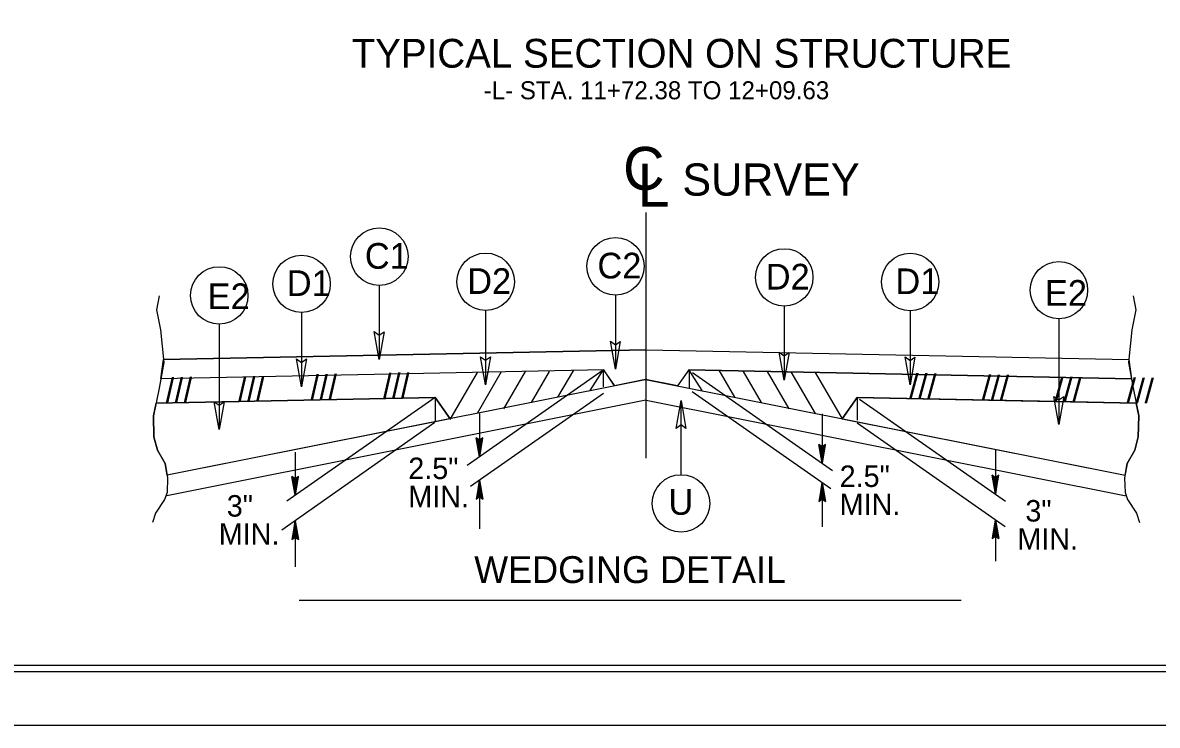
# Model space of a CAD drawing. Extents: x 575722 to 576066, y -53107 to -52774.
# Drawn here: x 575878.83 to 575926.06, y -52908.76 to -52879.49 of the extents above; entities that cross this region are included whole.
import ezdxf

# ---------------------------------------------------------------- set-up
doc = ezdxf.new("R2010")
doc.units = 0
for name, color, linetype in [('Prop Dimension Text', 7, 'Continuous'), ('Prop DSN Text', 7, 'Continuous'), ('Sheet Cutting Line CELL', 7, 'Continuous'), ('Sheet Plot Border Inside CELL', 7, 'Continuous'), ('Sheet Plot Border Outside CELL', 7, 'Continuous'), ('Sheet Typical CELL', 7, 'Continuous'), ('Typical Text Label CELL', 7, 'Continuous')]:
    doc.layers.add(name, color=color, linetype=linetype)

msp = doc.modelspace()

# ---------------------------------------------------------------- linework, layer by layer
at = {"layer": 'Prop DSN Text'}
for p, q in [((575904.783, -52897.636), (575904.783, -52887.4)), ((575893.675, -52890.431), (575893.675, -52893.523)), ((575903.509, -52890.835), (575903.509, -52893.927)), ((575904.783, -52897.636), (575904.783, -52890.645)), ((575910.532, -52891.296), (575910.532, -52894.388)), ((575890.439, -52891.566), (575890.439, -52894.658)), ((575898.101, -52891.479), (575898.101, -52894.571)), ((575915.776, -52891.487), (575915.776, -52894.579)), ((575921.968, -52891.827), (575921.968, -52896.224)), ((575887.012, -52892.048), (575887.012, -52896.444)), ((575904.783, -52893.114), (575884.694, -52893.515)), ((575884.694, -52893.515), (575904.783, -52893.114)), ((575904.783, -52893.114), (575924.873, -52893.515)), ((575904.785, -52893.114), (575924.873, -52893.515)), ((575884.58, -52894.322), (575884.694, -52893.515)), ((575924.873, -52893.515), (575924.988, -52894.322)), ((575903.021, -52893.954), (575884.58, -52894.322)), ((575903.021, -52893.954), (575884.58, -52894.322)), ((575897.752, -52894.06), (575896.61, -52896.016)), ((575902.998, -52893.969), (575897.338, -52897.933)), ((575898.754, -52894.039), (575897.744, -52895.774)), ((575899.747, -52894.02), (575898.84, -52895.574)), ((575900.747, -52894.022), (575899.995, -52895.309)), ((575901.755, -52893.97), (575901.1, -52895.093)), ((575902.45, -52894.813), (575902.995, -52893.961)), ((575902.995, -52893.961), (575902.995, -52894.661)), ((575903.472, -52894.616), (575903.021, -52893.954)), ((575903.021, -52893.975), (575903.472, -52894.616)), ((575906.56, -52893.954), (575906.094, -52894.616)), ((575906.56, -52893.954), (575906.094, -52894.616)), ((575906.531, -52893.969), (575906.56, -52893.97)), ((575906.56, -52893.954), (575924.988, -52894.322)), ((575924.988, -52894.322), (575906.56, -52893.954)), ((575907.117, -52894.813), (575906.572, -52893.961)), ((575906.572, -52893.961), (575906.572, -52894.732)), ((575906.714, -52894.061), (575912.545, -52898.145)), ((575907.811, -52893.97), (575908.467, -52895.093)), ((575908.819, -52894.022), (575909.571, -52895.309)), ((575909.819, -52894.02), (575910.727, -52895.574)), ((575910.812, -52894.039), (575911.823, -52895.774)), ((575911.816, -52894.06), (575912.94, -52895.987)), ((575904.813, -52894.349), (575884.845, -52898.344)), ((575904.753, -52894.349), (575903.472, -52894.616)), ((575904.753, -52894.349), (575924.722, -52898.344)), ((575906.094, -52894.616), (575904.753, -52894.349)), ((575895.995, -52895.102), (575884.384, -52895.334)), ((575884.384, -52895.334), (575895.995, -52895.102)), ((575895.995, -52895.102), (575889.83, -52899.419)), ((575896.627, -52895.989), (575895.995, -52895.102)), ((575895.995, -52895.102), (575895.995, -52896.115)), ((575895.995, -52895.102), (575896.625, -52895.987)), ((575903.011, -52894.938), (575897.472, -52898.816)), ((575906.706, -52894.855), (575912.48, -52898.898)), ((575913.571, -52895.102), (575912.94, -52895.987)), ((575912.941, -52895.987), (575913.571, -52895.102)), ((575913.571, -52895.102), (575925.183, -52895.334)), ((575913.571, -52895.102), (575913.571, -52896.043)), ((575921.852, -52895.268), (575913.571, -52895.102)), ((575913.665, -52895.167), (575919.746, -52899.426)), ((575904.775, -52895.209), (575884.838, -52899.197)), ((575904.791, -52895.209), (575924.774, -52899.206)), ((575906.237, -52898.321), (575906.237, -52895.229)), ((575925.183, -52895.334), (575921.852, -52895.268)), ((575895.995, -52896.113), (575893.973, -52896.518)), ((575896.625, -52895.987), (575895.995, -52896.113)), ((575897.853, -52895.776), (575897.853, -52897.571)), ((575912.119, -52895.788), (575912.119, -52897.846)), ((575912.94, -52895.987), (575915.594, -52896.518)), ((575893.973, -52896.518), (575884.845, -52898.344)), ((575895.99, -52896.147), (575889.617, -52900.632)), ((575913.571, -52896.166), (575919.735, -52900.484)), ((575915.594, -52896.518), (575924.722, -52898.344)), ((575897.853, -52897.571), (575897.714, -52896.784)), ((575897.853, -52896.887), (575897.714, -52896.784)), ((575897.853, -52897.571), (575897.734, -52896.799)), ((575897.754, -52896.814), (575897.853, -52897.571)), ((575897.853, -52897.571), (575897.773, -52896.828)), ((575897.794, -52896.843), (575897.853, -52897.571)), ((575897.853, -52897.571), (575897.814, -52896.857)), ((575897.834, -52896.872), (575897.853, -52897.571)), ((575897.853, -52897.571), (575897.993, -52896.784)), ((575897.993, -52896.784), (575897.853, -52896.887)), ((575897.973, -52896.799), (575897.853, -52897.571)), ((575897.853, -52897.571), (575897.952, -52896.814)), ((575897.932, -52896.828), (575897.853, -52897.571)), ((575897.853, -52897.571), (575897.912, -52896.843)), ((575897.893, -52896.857), (575897.853, -52897.571)), ((575897.853, -52897.571), (575897.873, -52896.872)), ((575897.853, -52896.887), (575897.853, -52897.571)), ((575912.119, -52897.846), (575911.98, -52897.058)), ((575912.119, -52897.161), (575911.98, -52897.058)), ((575912.119, -52897.846), (575912.258, -52897.058)), ((575912.258, -52897.058), (575912.119, -52897.161)), ((575890.177, -52897.387), (575890.177, -52899.177)), ((575912.119, -52897.846), (575912, -52897.073)), ((575912.02, -52897.088), (575912.119, -52897.846)), ((575912.119, -52897.846), (575912.039, -52897.102)), ((575912.059, -52897.117), (575912.119, -52897.846)), ((575912.119, -52897.846), (575912.079, -52897.131)), ((575912.098, -52897.146), (575912.119, -52897.846)), ((575912.237, -52897.073), (575912.119, -52897.846)), ((575912.119, -52897.846), (575912.218, -52897.088)), ((575912.198, -52897.102), (575912.119, -52897.846)), ((575912.119, -52897.846), (575912.178, -52897.117)), ((575912.159, -52897.131), (575912.119, -52897.846)), ((575912.119, -52897.846), (575912.139, -52897.146)), ((575912.119, -52897.161), (575912.119, -52897.846)), ((575919.328, -52897.271), (575919.328, -52899.132)), ((575890.177, -52899.177), (575890.037, -52898.389)), ((575890.177, -52898.49), (575890.037, -52898.389)), ((575890.177, -52899.177), (575890.057, -52898.403)), ((575890.079, -52898.418), (575890.177, -52899.177)), ((575890.177, -52899.177), (575890.098, -52898.432)), ((575890.118, -52898.446), (575890.177, -52899.177)), ((575890.177, -52899.177), (575890.138, -52898.461)), ((575890.157, -52898.476), (575890.177, -52899.177)), ((575890.177, -52899.177), (575890.316, -52898.389)), ((575890.316, -52898.389), (575890.177, -52898.49)), ((575890.296, -52898.403), (575890.177, -52899.177)), ((575890.177, -52899.177), (575890.277, -52898.418)), ((575890.257, -52898.432), (575890.177, -52899.177)), ((575890.177, -52899.177), (575890.236, -52898.446)), ((575890.217, -52898.461), (575890.177, -52899.177)), ((575890.177, -52899.177), (575890.197, -52898.476)), ((575919.328, -52899.132), (575919.189, -52898.346)), ((575919.328, -52898.447), (575919.189, -52898.346)), ((575919.328, -52899.132), (575919.209, -52898.36)), ((575919.228, -52898.374), (575919.328, -52899.132)), ((575919.328, -52899.132), (575919.248, -52898.388)), ((575919.268, -52898.404), (575919.328, -52899.132)), ((575919.328, -52899.132), (575919.287, -52898.418)), ((575919.307, -52898.433), (575919.328, -52899.132)), ((575919.328, -52899.132), (575919.467, -52898.346)), ((575919.467, -52898.346), (575919.328, -52898.447)), ((575919.446, -52898.36), (575919.328, -52899.132)), ((575919.328, -52899.132), (575919.426, -52898.374)), ((575919.407, -52898.388), (575919.328, -52899.132)), ((575919.328, -52899.132), (575919.387, -52898.404)), ((575919.367, -52898.418), (575919.328, -52899.132)), ((575919.328, -52899.132), (575919.347, -52898.433)), ((575919.328, -52898.447), (575919.328, -52899.132)), ((575890.177, -52898.49), (575890.177, -52899.177)), ((575897.853, -52898.549), (575897.714, -52899.337)), ((575897.734, -52899.321), (575897.853, -52898.549)), ((575897.853, -52898.549), (575897.754, -52899.307)), ((575897.773, -52899.291), (575897.853, -52898.549)), ((575897.853, -52898.549), (575897.794, -52899.278)), ((575897.814, -52899.264), (575897.853, -52898.549)), ((575897.853, -52898.549), (575897.834, -52899.249)), ((575897.853, -52898.549), (575897.853, -52900.571)), ((575897.853, -52898.549), (575897.993, -52899.337)), ((575897.853, -52899.234), (575897.853, -52898.549)), ((575897.873, -52899.249), (575897.853, -52898.549)), ((575897.853, -52898.549), (575897.893, -52899.264)), ((575897.912, -52899.278), (575897.853, -52898.549)), ((575897.853, -52898.549), (575897.932, -52899.291)), ((575897.952, -52899.307), (575897.853, -52898.549)), ((575897.853, -52898.549), (575897.973, -52899.321)), ((575912.119, -52898.645), (575911.98, -52899.433)), ((575912, -52899.417), (575912.119, -52898.645)), ((575912.119, -52898.645), (575912.02, -52899.403)), ((575912.039, -52899.387), (575912.119, -52898.645)), ((575912.119, -52898.645), (575912.059, -52899.374)), ((575912.079, -52899.36), (575912.119, -52898.645)), ((575912.119, -52898.645), (575912.098, -52899.345)), ((575912.119, -52898.645), (575912.119, -52900.486)), ((575912.119, -52898.645), (575912.258, -52899.433)), ((575912.119, -52899.33), (575912.119, -52898.645)), ((575912.139, -52899.345), (575912.119, -52898.645)), ((575912.119, -52898.645), (575912.159, -52899.36)), ((575912.178, -52899.374), (575912.119, -52898.645)), ((575912.119, -52898.645), (575912.198, -52899.387)), ((575912.218, -52899.403), (575912.119, -52898.645)), ((575912.119, -52898.645), (575912.237, -52899.417)), ((575897.714, -52899.337), (575897.853, -52899.234)), ((575897.853, -52899.234), (575897.993, -52899.337)), ((575911.98, -52899.433), (575912.119, -52899.33)), ((575912.119, -52899.33), (575912.258, -52899.433)), ((575890.177, -52900.239), (575890.037, -52901.026)), ((575890.059, -52901.012), (575890.177, -52900.239)), ((575890.177, -52900.239), (575890.079, -52900.997)), ((575890.098, -52900.982), (575890.177, -52900.239)), ((575890.177, -52900.239), (575890.118, -52900.967)), ((575890.138, -52900.954), (575890.177, -52900.239)), ((575890.177, -52900.239), (575890.157, -52900.94)), ((575890.177, -52900.239), (575890.177, -52902.153)), ((575890.177, -52900.239), (575890.316, -52901.026)), ((575890.177, -52900.924), (575890.177, -52900.239)), ((575890.197, -52900.94), (575890.177, -52900.239)), ((575890.177, -52900.239), (575890.217, -52900.954)), ((575890.237, -52900.967), (575890.177, -52900.239)), ((575890.177, -52900.239), (575890.257, -52900.982)), ((575890.277, -52900.997), (575890.177, -52900.239)), ((575890.177, -52900.239), (575890.296, -52901.012)), ((575919.328, -52900.197), (575919.189, -52900.985)), ((575919.209, -52900.97), (575919.328, -52900.197)), ((575919.328, -52900.197), (575919.228, -52900.956)), ((575919.248, -52900.941), (575919.328, -52900.197)), ((575919.328, -52900.197), (575919.268, -52900.926)), ((575919.287, -52900.911), (575919.328, -52900.197)), ((575919.328, -52900.197), (575919.307, -52900.897)), ((575919.328, -52900.197), (575919.328, -52901.926)), ((575919.328, -52900.197), (575919.467, -52900.985)), ((575919.328, -52900.882), (575919.328, -52900.197)), ((575919.347, -52900.897), (575919.328, -52900.197)), ((575919.328, -52900.197), (575919.367, -52900.911)), ((575919.387, -52900.926), (575919.328, -52900.197)), ((575919.328, -52900.197), (575919.407, -52900.941)), ((575919.426, -52900.956), (575919.328, -52900.197)), ((575919.328, -52900.197), (575919.446, -52900.97)), ((575890.037, -52901.026), (575890.177, -52900.924)), ((575890.177, -52900.924), (575890.316, -52901.026)), ((575919.189, -52900.985), (575919.328, -52900.882)), ((575919.328, -52900.882), (575919.467, -52900.985))]:
    msp.add_line(p, q, dxfattribs=at)
for points in [[(575884.508, -52890.864), (575884.4, -52891.453), (575884.561, -52892.289), (575884.703, -52893.644), (575884.508, -52894.713), (575884.276, -52895.871), (575884.294, -52896.745), (575884.437, -52897.296), (575884.758, -52897.85), (575884.864, -52898.455), (575884.847, -52899.061), (575884.739, -52899.347), (575884.366, -52899.917), (575884.241, -52900.309)], [(575925.059, -52890.864), (575925.166, -52891.453), (575925.005, -52892.289), (575924.863, -52893.644), (575925.059, -52894.713), (575925.291, -52895.871), (575925.273, -52896.745), (575925.13, -52897.296), (575924.809, -52897.85), (575924.703, -52898.455), (575924.72, -52899.061), (575924.827, -52899.347), (575925.2, -52899.917), (575925.325, -52900.309)], [(575884.844, -52898.344), (575884.758, -52897.85), (575884.437, -52897.296), (575884.294, -52896.745), (575884.276, -52895.871), (575884.383, -52895.334)], [(575924.722, -52898.344), (575924.809, -52897.85), (575925.13, -52897.296), (575925.273, -52896.745), (575925.291, -52895.871), (575925.183, -52895.334)]]:
    msp.add_lwpolyline(points, dxfattribs=at)
for points in [[(575893.875, -52892.363), (575893.675, -52893.523), (575893.469, -52892.356), (575893.675, -52892.505)], [(575893.875, -52892.363), (575893.675, -52893.523), (575893.469, -52892.356), (575893.675, -52892.505)], [(575903.709, -52892.767), (575903.509, -52893.927), (575903.303, -52892.761), (575903.509, -52892.909)], [(575903.709, -52892.767), (575903.509, -52893.927), (575903.303, -52892.761), (575903.509, -52892.909)], [(575910.732, -52893.228), (575910.532, -52894.388), (575910.326, -52893.222), (575910.532, -52893.37)], [(575910.732, -52893.228), (575910.532, -52894.388), (575910.326, -52893.222), (575910.532, -52893.37)], [(575890.639, -52893.498), (575890.439, -52894.658), (575890.233, -52893.491), (575890.439, -52893.639)], [(575890.639, -52893.498), (575890.439, -52894.658), (575890.233, -52893.491), (575890.439, -52893.639)], [(575898.301, -52893.411), (575898.101, -52894.571), (575897.895, -52893.405), (575898.101, -52893.553)], [(575898.301, -52893.411), (575898.101, -52894.571), (575897.895, -52893.405), (575898.101, -52893.553)], [(575915.976, -52893.419), (575915.776, -52894.579), (575915.57, -52893.413), (575915.776, -52893.561)], [(575915.976, -52893.419), (575915.776, -52894.579), (575915.57, -52893.413), (575915.776, -52893.561)], [(575922.167, -52895.064), (575921.968, -52896.224), (575921.761, -52895.058), (575921.968, -52895.206)], [(575887.211, -52895.285), (575887.012, -52896.444), (575886.805, -52895.278), (575887.012, -52895.426)], [(575887.211, -52895.285), (575887.012, -52896.444), (575886.805, -52895.278), (575887.012, -52895.426)], [(575906.037, -52896.389), (575906.237, -52895.229), (575906.443, -52896.395), (575906.237, -52896.247)], [(575906.037, -52896.389), (575906.237, -52895.229), (575906.443, -52896.395), (575906.237, -52896.247)]]:
    msp.add_lwpolyline(points, close=True, dxfattribs=at)
for centre in [(575893.675, -52889.235), (575903.509, -52889.639), (575910.532, -52890.1), (575890.439, -52890.37), (575898.102, -52890.283), (575915.776, -52890.291), (575921.967, -52890.631), (575887.011, -52890.852), (575906.237, -52899.517)]:
    msp.add_circle(centre, 1.196, dxfattribs=at)
at = {"layer": 'Sheet Cutting Line CELL'}
msp.add_line((575796.575, -52908.762), (575964.975, -52908.762), dxfattribs=at)
at = {"layer": 'Sheet Plot Border Inside CELL'}
msp.add_lwpolyline([(575964.525, -52801.007), (575797.875, -52801.007), (575797.875, -52906.517), (575964.525, -52906.517)], close=True, dxfattribs=at)
at = {"layer": 'Sheet Plot Border Outside CELL'}
msp.add_lwpolyline([(575964.975, -52798.762), (575796.575, -52798.762), (575796.575, -52908.762), (575964.975, -52908.762)], close=True, dxfattribs=at)
at = {"layer": 'Sheet Typical CELL'}
msp.add_lwpolyline([(575963.275, -52801.262), (575813.275, -52801.262), (575813.275, -52906.262), (575963.275, -52906.262)], close=True, dxfattribs=at)
at = {"layer": 'Typical Text Label CELL'}
msp.add_line((575890.337, -52903.542), (575917.902, -52903.542), dxfattribs=at)

# ---------------------------------------------------------------- texts
at = {"layer": 'Prop Dimension Text'}
msp.add_text('TYPICAL SECTION ON STRUCTURE', height=1.2, dxfattribs=at).set_placement((575892.525, -52881.363))
at = {"layer": 'Prop DSN Text'}
for s, height, p in [('-L- STA. 11+72.38 TO 12+09.63', 0.75, (575898.023, -52882.679)), ('C', 1.79, (575903.823, -52886.454)), ('L', 1.79, (575904.424, -52887.157)), ('SURVEY ', 1.3422, (575906.293, -52886.695)), ('C1', 1.0708, (575893.075, -52889.74)), ('C2', 1.0708, (575902.756, -52890.145)), ('D1', 1.0708, (575889.824, -52890.875)), ('D2', 1.0708, (575897.333, -52890.789)), ('D2', 1.0708, (575909.763, -52890.606)), ('D1', 1.0708, (575915.161, -52890.797)), ('E2', 1.0708, (575886.531, -52891.422)), ('E2', 1.0708, (575921.385, -52891.283)), ('2.5"', 0.8948, (575894.882, -52898.503)), ('2.5"', 0.8948, (575912.84, -52898.831)), ('MIN.', 0.8948, (575894.882, -52899.676)), ('U', 1.071, (575905.714, -52899.991)), (' 3"', 0.8948, (575886.994, -52900.066)), ('MIN.', 0.8948, (575912.84, -52900.004)), (' 3"', 0.8948, (575920.239, -52900.272)), ('MIN.', 0.8948, (575886.994, -52901.239)), ('MIN.', 0.8948, (575920.239, -52901.445))]:
    msp.add_text(s, height=height, dxfattribs=at).set_placement(p)
for height, rotation, p in [(1.0074, 1.1447, (575884.784, -52895.32)), (1.0074, 1.1464, (575887.795, -52895.285)), (1.007, 1.1445, (575890.812, -52895.196)), (1.0071, 1.1463, (575893.833, -52895.134)), (1.0071, 358.8553, (575915.734, -52895.134)), (1.007, 358.8536, (575918.755, -52895.196)), (1.0074, 358.8554, (575921.772, -52895.285)), (1.0074, 358.8537, (575924.782, -52895.32))]:
    msp.add_text('/// ', height=height, rotation=rotation, dxfattribs=at).set_placement(p)
at = {"layer": 'Typical Text Label CELL'}
msp.add_text('WEDGING DETAIL', height=1.12, dxfattribs=at).set_placement((575897.626, -52902.835))

doc.saveas('drawing.dxf')
